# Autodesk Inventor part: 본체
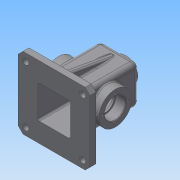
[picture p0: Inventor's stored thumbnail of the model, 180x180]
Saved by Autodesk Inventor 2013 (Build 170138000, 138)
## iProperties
Created: 2018-10
Part Number: 본체
Material: 일반
Document SubType Name: Modeling
Designer: Administrator
Density: 1 g/cm^3
Author: Administrator
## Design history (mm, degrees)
sketch "스케치1"
  geometry: L1 (32.5, -32.5)-(-32.5, -32.5); L2 (-32.5, -32.5)-(-32.5, 32.5); L3 (-32.5, 32.5)-(32.5, 32.5); L4 (32.5, 32.5)-(32.5, -32.5); L5 (32.5, -32.5)-(-32.5, 32.5); L6 (-32.5, -32.5)-(32.5, 32.5); 1 further point
  constraints: 12 end point, 2 midpoint, 2 parallel, 1 horizontal, 1 perpendicular
  dimensions: "d0" = 65 distance of L2.end L3.end; "d1" = 65 distance of L1.end L2.end
extrude "돌출1" new body sketch "스케치1" distance "d2" = 55; taper "d4" = 0 deg; dims "d3" = 55, "d5" = 0
feature "쉘1" dims "d6" = 5
fillet "모깎기2" dims "d8" = 3
node "작업 평면1"
sketch "스케치2"
  geometry: C1 r 20 at (0, 0); 1 further point
  constraints: 1 centre point, 1 coincident
  dimensions: "d10" = 40 diameter of C1
extrude "돌출2" join sketch "스케치2" stored distance "d11" = 55; taper "d12" = 7 deg
hole "구멍1" diameter "d15" = 22.835; stored, may be unused: countersink angle "d19" = 90 deg, drill point angle "d21" = 118 deg; dims "d13" = 10, "d14" = 10, "d16" = 50, "d17" = 4, "d18" = 2, "d20" = 50
sketch "스케치3"
  geometry: L1 (-32.5, -32.5)-(32.5, -32.5) reference; L2 (32.5, -32.5)-(32.5, 32.5) reference; L3 (32.5, 32.5)-(-32.5, 32.5) reference; L4 (-32.5, 32.5)-(-32.5, -32.5) reference; L5 (60, -60)-(-60, -60); L6 (-60, -60)-(-60, 60); L7 (-60, 60)-(60, 60); L8 (60, 60)-(60, -60); L9 (60, -60)-(-60, 60); L10 (-60, -60)-(60, 60); A1 r 8 centre (24.5, -24.5) between (24.5, -32.5) and (32.5, -24.5) reference; A2 r 8 centre (24.5, 24.5) between (32.5, 24.5) and (24.5, 32.5) reference; A3 r 8 centre (-24.5, 24.5) between (-24.5, 32.5) and (-32.5, 24.5) reference; A4 r 8 centre (-24.5, -24.5) between (-32.5, -24.5) and (-24.5, -32.5) reference; 1 further point
  constraints: 12 end point, 2 midpoint, 2 parallel, 1 horizontal, 1 perpendicular
  dimensions: "d22" = 120 distance of L6.end L7.end; "d23" = 120 distance of L5.end L6.end
extrude "돌출3" join sketch "스케치3" distance "d24" = 10; taper "d25" = 0 deg
chamfer "모따기1" distance "d26" = 8; stored, may be unused: second distance "d27" = 2, angle "d28" = 45 deg
sketch "스케치4"
  geometry: L1 (-60, 52)-(-60, -52) reference; L2 (52, 60)-(-52, 60) reference; C1 r 5 at (-47.5, 47.5); 1 further point
  constraints: 1 centre point
  dimensions: "d29" = 10 diameter of C1; "d30" = 12.5 distance from line of C1.centre L1; "d31" = 12.5 distance from line of C1.centre L2
extrude "돌출4" cut sketch "스케치4" stored distance "d32" = 10; taper "d33" = 0 deg
sketch "스케치5"
  geometry: L1 (-19.5, -110)-(84.5, -110) reference; C1 r 27.5 at (32.5, -55); 1 further point
  constraints: 1 centre point, 1 coincident
  dimensions: "d34" = 55 diameter of C1; "d35" = 55 distance from line of L1 C1.centre
extrude "돌출5" join sketch "스케치5" distance "d36" = 15; taper "d37" = 0 deg
hole "구멍2" diameter "d40" = 30; stored, may be unused: countersink angle "d44" = 90 deg, drill point angle "d46" = 118 deg; dims "d38" = 10, "d39" = 10, "d41" = 50, "d42" = 35, "d43" = 17, "d45" = 50
sketch "스케치6"
  geometry: C1 r 17.5 at (0, 0) reference; 1 further point
  constraints: 1 vertical alignment
  dimensions: "d47" = 21 distance of C1.centre point (0, 21)
hole "구멍3" sketch "스케치6" at (0, 21) diameter "d48" = 3.242; stored, may be unused: countersink angle "d52" = 90 deg, drill point angle "d54" = 118 deg; dims "d49" = 8, "d50" = 35, "d51" = 17, "d53" = 10
chamfer "모따기2" distance "d58" = 1; stored, may be unused: second distance "d59" = 2, angle "d60" = 45 deg
fillet "모깎기3" dims "d61" = 8
sketch "스케치7"
  geometry: L1 (65, 11.418)-(50, 11.418) reference; L2 (50, 11.418)-(50, 24.5) reference; L3 (47, 27.5)-(-55, 27.5) reference; L4 (-55, 27.5)-(-55, 60) reference; L5 (-55, 60)-(-45, 60) reference; L6 (-45, 60)-(-45, 32.5) reference; L7 (-45, 32.5)-(47, 32.5) reference; L8 (55, 24.5)-(55, 21.228) reference; L9 (55, 21.228)-(65, 20) reference; L10 (65, 20)-(65, 11.418) reference; L11 (50, -11.418)-(65, -11.418) reference; L12 (65, -11.418)-(65, -20) reference; L13 (65, -20)-(55, -21.228) reference; L14 (55, -21.228)-(55, -24.5) reference; L15 (47, -32.5)-(-45, -32.5) reference; L16 (-45, -32.5)-(-45, -60) reference; L17 (-45, -60)-(-55, -60) reference; L18 (-55, -60)-(-55, -27.5) reference; L19 (-55, -27.5)-(47, -27.5) reference; L20 (50, -24.5)-(50, -11.418) reference; L21 (-45, 48)-(-13.889, 42.514); A1 r 3 centre (47, 24.5) between (50, 24.5) and (47, 27.5) reference; A2 r 8 centre (47, 24.5) between (55, 24.5) and (47, 32.5) reference; A3 r 8 centre (47, -24.5) between (47, -32.5) and (55, -24.5) reference; A4 r 3 centre (47, -24.5) between (47, -27.5) and (50, -24.5) reference; 1 further point
  constraints: 2 end point, 1 point on line
  dimensions: "d63" = 12 distance from line of L21.start L5; "d64" = 100 deg angle of L6 L21
feature "리브1" sketch "스케치7" dims "d65" = 1, "d66" = 10, "d67" = 0, "d68" = 0, "d69" = 1, "d70" = 1
fillet "모깎기5" dims "d71" = 3
fillet "모깎기6" dims "d72" = 3
sketch "스케치8"
  geometry: L1 (36.526, -21)-(37.5, -22.621) reference; L2 (37.5, -22.621)-(47.5, -22.621) reference; L3 (47.5, -22.621)-(47.5, -27.5) reference; L4 (47.5, -27.5)-(32.5, -27.5) reference; L5 (32.5, -27.5)-(32.5, -45) reference; L6 (32.5, -45)-(60, -45) reference; L7 (60, -45)-(60, -55) reference; L8 (60, -55)-(27.5, -55) reference; L9 (27.5, -55)-(27.5, -15) reference; L10 (27.5, -15)-(30.5, -15) reference; L11 (30.5, -15)-(30.5, -17.5) reference; L12 (30.5, -17.5)-(46.5, -17.5) reference; L13 (46.5, -17.5)-(47.5, -18.5) reference; L14 (47.5, -18.5)-(47.5, -19.379) reference; L15 (47.5, -19.379)-(37.5, -19.379) reference; L16 (37.5, -19.379)-(36.526, -21) reference; L17 (37.5, 22.621)-(36.526, 21) reference; L18 (36.526, 21)-(37.5, 19.379) reference; L19 (37.5, 19.379)-(47.5, 19.379) reference; L20 (47.5, 19.379)-(47.5, 18.5) reference; L21 (47.5, 18.5)-(46.5, 17.5) reference; L22 (46.5, 17.5)-(30.5, 17.5) reference; L23 (30.5, 17.5)-(30.5, 15) reference; L24 (30.5, 15)-(27.5, 15) reference; L25 (27.5, 15)-(27.5, 47) reference; L26 (24.5, 50)-(11.418, 50) reference; L27 (11.418, 50)-(11.418, 65) reference; L28 (11.418, 65)-(20, 65) reference; L29 (20, 65)-(21.228, 55) reference; L30 (21.228, 55)-(24.5, 55) reference; L31 (32.5, 47)-(32.5, 27.5) reference; L32 (32.5, 27.5)-(47.5, 27.5) reference; L33 (47.5, 27.5)-(47.5, 22.621) reference; L34 (47.5, 22.621)-(37.5, 22.621) reference; L35 (-37.5, -22.621)-(-36.526, -21) reference; L36 (-36.526, -21)-(-37.5, -19.379) reference; L37 (-37.5, -19.379)-(-47.5, -19.379) reference; L38 (-47.5, -19.379)-(-47.5, -18.5) reference; L39 (-47.5, -18.5)-(-46.5, -17.5) reference; L40 (-46.5, -17.5)-(-30.5, -17.5) reference; L41 (-30.5, -17.5)-(-30.5, -15) reference; L42 (-30.5, -15)-(-27.5, -15) reference; L43 (-27.5, -15)-(-27.5, -55) reference; L44 (-27.5, -55)-(-60, -55) reference; L45 (-60, -55)-(-60, -45) reference; L46 (-60, -45)-(-32.5, -45) reference; L47 (-32.5, -45)-(-32.5, -27.5) reference; L48 (-32.5, -27.5)-(-47.5, -27.5) reference; L49 (-47.5, -27.5)-(-47.5, -22.621) reference; L50 (-47.5, -22.621)-(-37.5, -22.621) reference; L51 (-36.526, 21)-(-37.5, 22.621) reference; L52 (-37.5, 22.621)-(-47.5, 22.621) reference; L53 (-47.5, 22.621)-(-47.5, 27.5) reference; L54 (-47.5, 27.5)-(-32.5, 27.5) reference; L55 (-32.5, 27.5)-(-32.5, 47) reference; L56 (-24.5, 55)-(-21.228, 55) reference; L57 (-21.228, 55)-(-20, 65) reference; L58 (-20, 65)-(-11.418, 65) reference; L59 (-11.418, 65)-(-11.418, 50) reference; L60 (-11.418, 50)-(-24.5, 50) reference; L61 (-27.5, 47)-(-27.5, 15) reference; L62 (-27.5, 15)-(-30.5, 15) reference; L63 (-30.5, 15)-(-30.5, 17.5) reference; L64 (-30.5, 17.5)-(-46.5, 17.5) reference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; A1 r 3 centre (24.5, 47) between (27.5, 47) and (24.5, 50) reference; A2 r 8 centre (24.5, 47) between (32.5, 47) and (24.5, 55) reference; A3 r 8 centre (-24.5, 47) between (-24.5, 55) and (-32.5, 47) reference; A4 r 3 centre (-24.5, 47) between (-24.5, 50) and (-27.5, 47) reference; 1 further point
  constraints: 2 end point, 1 perpendicular, 1 point on line
  dimensions: "d74" = 15 distance between parallel lines of L43 L69
feature "리브2" sketch "스케치8" dims "d75" = 1, "d76" = 6, "d77" = 0, "d78" = 0, "d79" = 1, "d80" = 1
fillet "모깎기8" dims "d82" = 3
fillet "모깎기9" dims "d83" = 3
fillet "모깎기10" dims "d84" = 3
fillet "모깎기11" dims "d85" = 3
sketch "스케치9"
  geometry: L1 (-8, 0)-(-8, -92) reference; L2 (4.5, 18)-(44.5, 18) reference; 1 further point
  constraints: 1 other
  dimensions: "d86" = 32.5 distance from line of point (24.5, -8) L1; "d87" = 26 distance from line of point (24.5, -8) L2
feature "엠보싱1" sketch "스케치9" dims "d88" = 0.5, "d89" = 0
fillet "모깎기12" dims "d90" = 0.3
fillet "모깎기13" dims "d91" = 3
fillet "모깎기14" dims "d92" = 1
node "솔리드1"
mirror "대칭1"
mirror "대칭2"
pattern_circular "원형 패턴1" dims angle "d56" = 360 deg
mirror "대칭3"
mirror "대칭4"
mirror "대칭5"
node "절단 모서리 투영1"
node "절단 모서리 투영2"
other parameters: "d9" = 65
